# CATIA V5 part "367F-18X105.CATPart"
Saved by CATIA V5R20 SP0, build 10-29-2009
Part number: 367F-18X105
Definition: NONE
Nomenclature: 367F-18X105
Source: Unknown
Description: 367F-18X105
Bounding box of the stored display mesh (mm): x 0 to 105, y -14 to 14, z -14 to 14
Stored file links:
  C:\Users\Utente\Desktop\IO LAVORO\3D X SITO CF\X SITO\PLASTICA\3D files 367\367F-18X105.CATPart
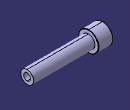
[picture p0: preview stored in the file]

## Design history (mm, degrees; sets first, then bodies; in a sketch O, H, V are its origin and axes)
Body1 "367F-18X105" (main body)
  Solid1: solid without history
